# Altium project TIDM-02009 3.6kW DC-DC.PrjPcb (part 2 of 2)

## Sheet TIDM-02009_DCDC_Power Stage.SchDoc
size A2; DocumentNumber: 1; SheetNumber: 1; SheetTotal: 3; PageSetup: Record=PageOptions¦CenterHorizontal=True¦CenterVertical=True¦PrintScale=0.69¦XCorrection=1.00¦YCorrection=1.00¦PrintKind=0¦BorderSize=5000000¦LeftOffset=0¦BottomOffset=0¦Orientation=2¦PaperLength=1000¦PaperWidth=1000¦Scale=100¦PaperSource=15¦PrintQuality=600¦MediaType=1¦DitherType=10¦PaperKind=Letter¦PrintScaleMode=1
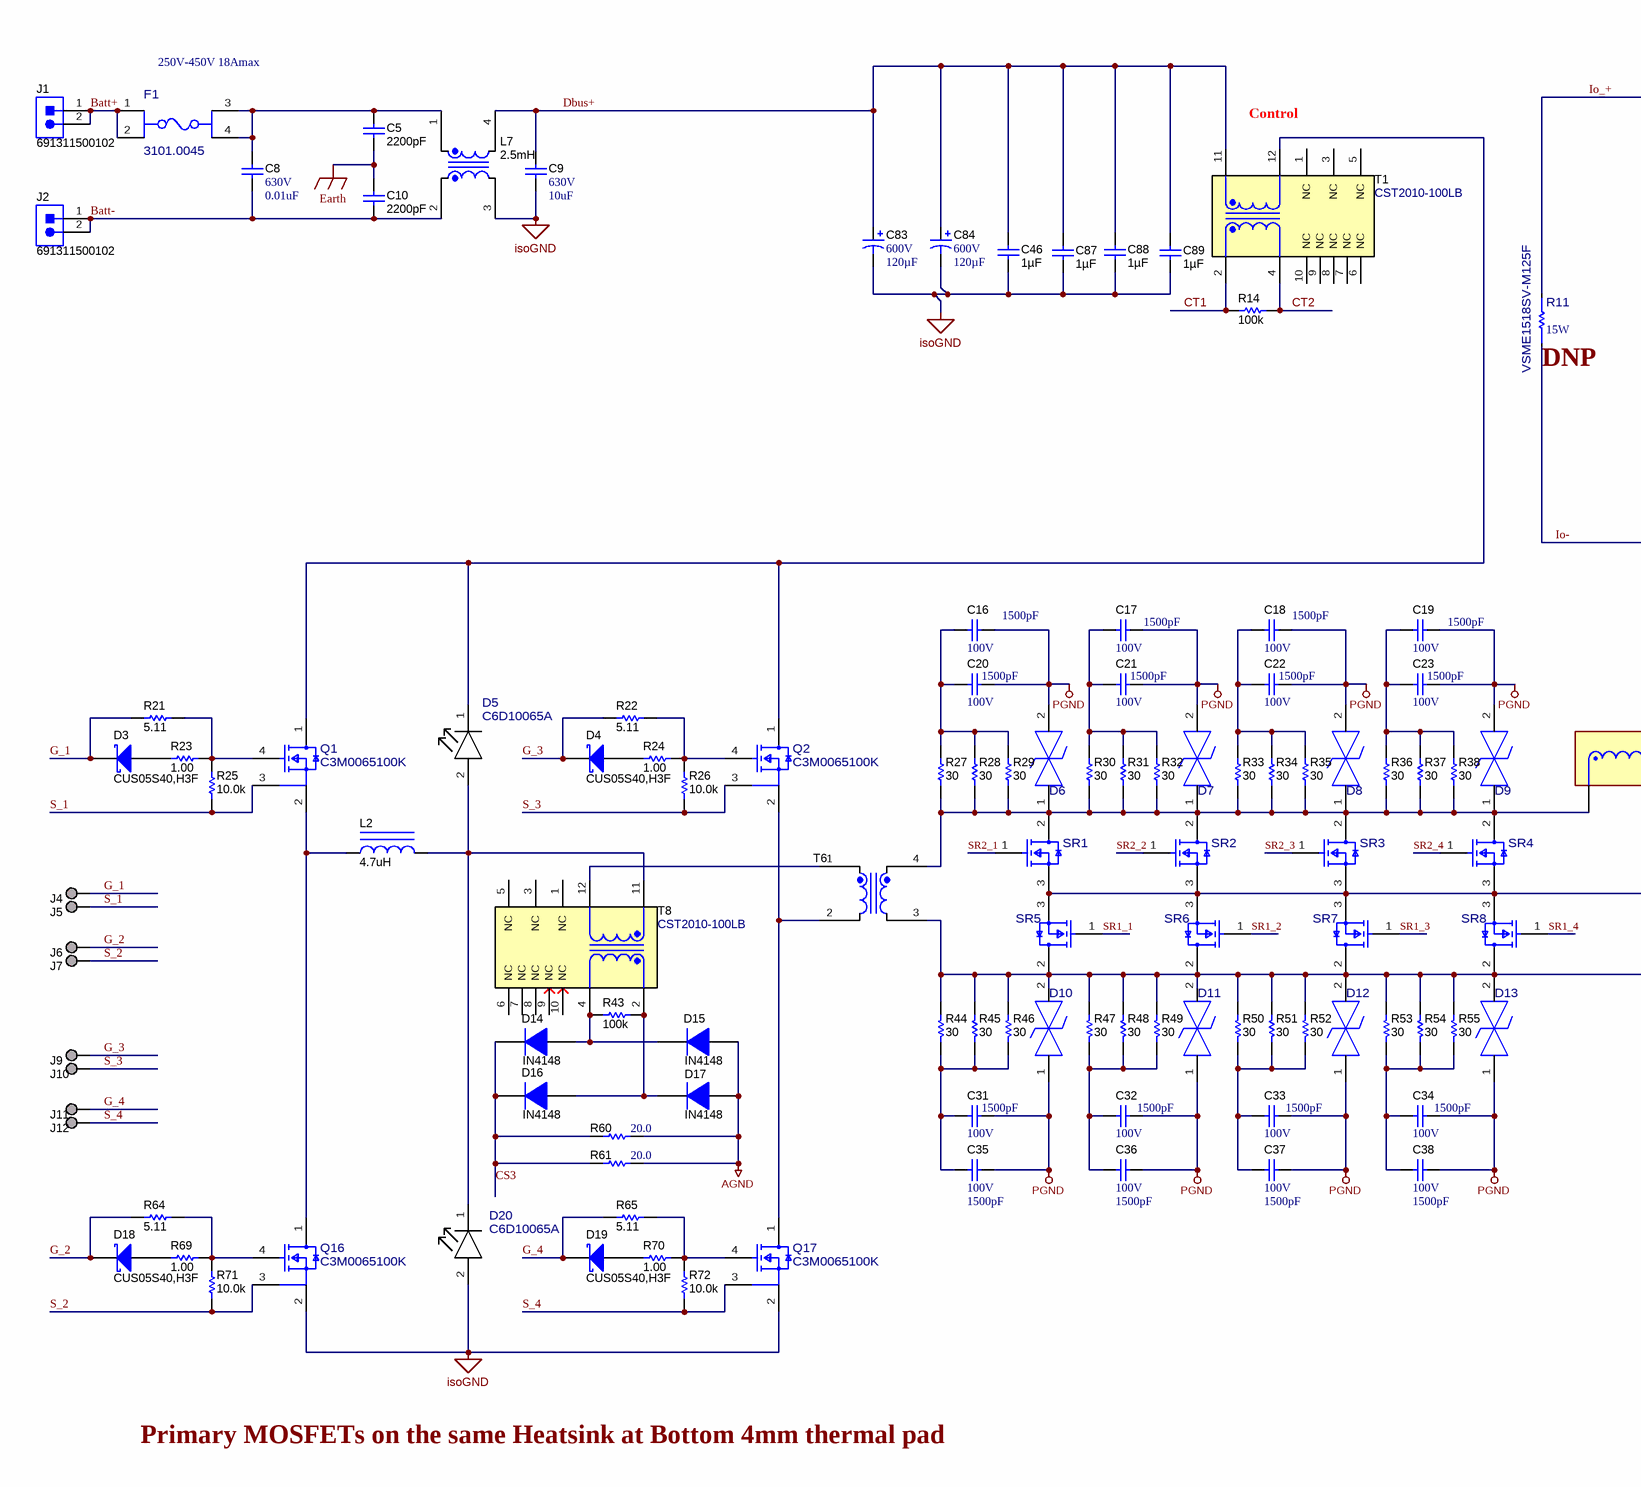
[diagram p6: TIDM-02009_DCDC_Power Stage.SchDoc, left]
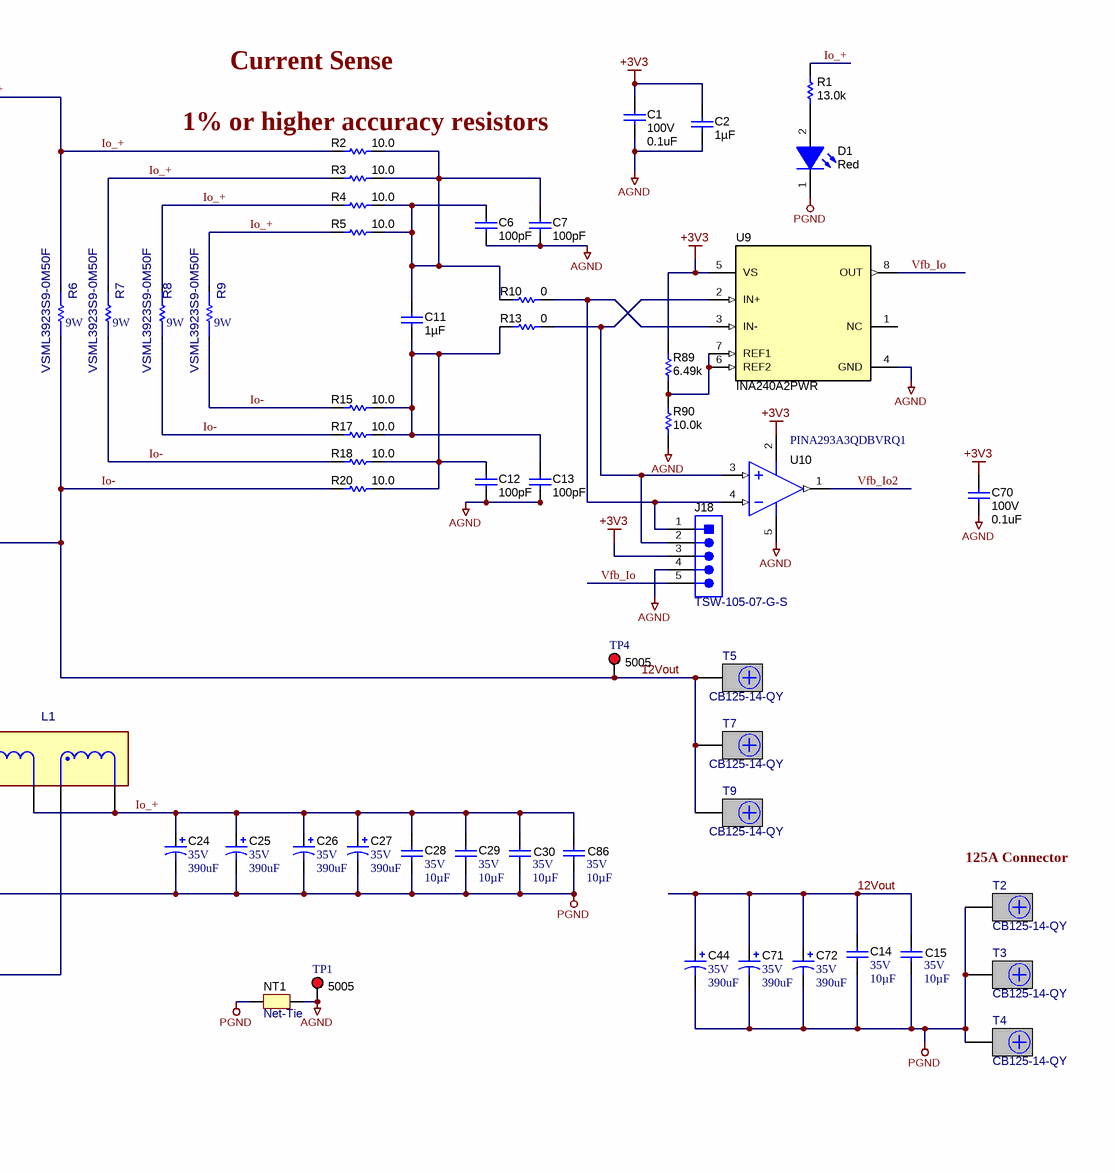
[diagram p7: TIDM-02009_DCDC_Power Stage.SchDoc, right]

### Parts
C1  VDC_V: 100V  ValueDisplayed: 0.1uF  [0603]  (hidden comment: GRM188R72A104KA35D)
C2  ValueDisplayed: 1µF  [0603]  (hidden comment: GRM188R71E105KA12D)
C5  ValueDisplayed: 2200pF  [E_900x700x900]  (hidden comment: DE6E3KJ222MN3A)
C6  ValueDisplayed: 100pF  [0603]  (hidden comment: 06035A101JAT2A)
C7  ValueDisplayed: 100pF  [0603]  (hidden comment: 06035A101JAT2A)
C8  VDC_V: 630V  ValueDisplayed: 0.01uF  [R73_1800x500x1100]  (hidden comment: R73PI21004000J)
C9  VDC_V: 630V  ValueDisplayed: 10uF  [B32926_42.5mm]  (hidden comment: B32926C3106K)
C10  ValueDisplayed: 2200pF  [E_900x700x900]  (hidden comment: DE6E3KJ222MN3A)
C11  ValueDisplayed: 1µF  [0603L]  (hidden comment: GRM188R71E105KA12D)
C12  ValueDisplayed: 100pF  [0603]  (hidden comment: 06035A101JAT2A)
C13  ValueDisplayed: 100pF  [0603]  (hidden comment: 06035A101JAT2A)
C14  VDC_V: 35V  ValueDisplayed: 10µF  [1210_270]  (hidden comment: GRM32ER7YA106KA12K)
C15  VDC_V: 35V  ValueDisplayed: 10µF  [1210_270]  (hidden comment: GRM32ER7YA106KA12K)
C16  VDC_V: 100V  ValueDisplayed: 1500pF  [1206]  (hidden comment: 12061C152KAT2A)
C17  VDC_V: 100V  ValueDisplayed: 1500pF  [1206]  (hidden comment: 12061C152KAT2A)
C18  VDC_V: 100V  ValueDisplayed: 1500pF  [1206]  (hidden comment: 12061C152KAT2A)
C19  VDC_V: 100V  ValueDisplayed: 1500pF  [1206]  (hidden comment: 12061C152KAT2A)
C20  VDC_V: 100V  ValueDisplayed: 1500pF  [1206]  (hidden comment: 12061C152KAT2A)
C21  VDC_V: 100V  ValueDisplayed: 1500pF  [1206]  (hidden comment: 12061C152KAT2A)
C22  VDC_V: 100V  ValueDisplayed: 1500pF  [1206]  (hidden comment: 12061C152KAT2A)
C23  VDC_V: 100V  ValueDisplayed: 1500pF  [1206]  (hidden comment: 12061C152KAT2A)
C24  VDC_V: 35V  ValueDisplayed: 390uF  [B41896_1250x2000]  (hidden comment: B41896C7397M000)
C25  VDC_V: 35V  ValueDisplayed: 390uF  [B41896_1250x2000]  (hidden comment: B41896C7397M000)
C26  VDC_V: 35V  ValueDisplayed: 390uF  [B41896_1250x2000]  (hidden comment: B41896C7397M000)
C27  VDC_V: 35V  ValueDisplayed: 390uF  [B41896_1250x2000]  (hidden comment: B41896C7397M000)
C28  VDC_V: 35V  ValueDisplayed: 10µF  [1210_270]  (hidden comment: GRM32ER7YA106KA12K)
C29  VDC_V: 35V  ValueDisplayed: 10µF  [1210_270]  (hidden comment: GRM32ER7YA106KA12K)
C30  VDC_V: 35V  ValueDisplayed: 10µF  [1210_270]  (hidden comment: GRM32ER7YA106KA12K)
C31  VDC_V: 100V  ValueDisplayed: 1500pF  [1206]  (hidden comment: 12061C152KAT2A)
C32  VDC_V: 100V  ValueDisplayed: 1500pF  [1206]  (hidden comment: 12061C152KAT2A)
C33  VDC_V: 100V  ValueDisplayed: 1500pF  [1206]  (hidden comment: 12061C152KAT2A)
C34  VDC_V: 100V  ValueDisplayed: 1500pF  [1206]  (hidden comment: 12061C152KAT2A)
C35  VDC_V: 100V  ValueDisplayed: 1500pF  [1206]  (hidden comment: 12061C152KAT2A)
C36  VDC_V: 100V  ValueDisplayed: 1500pF  [1206]  (hidden comment: 12061C152KAT2A)
C37  VDC_V: 100V  ValueDisplayed: 1500pF  [1206]  (hidden comment: 12061C152KAT2A)
C38  VDC_V: 100V  ValueDisplayed: 1500pF  [1206]  (hidden comment: 12061C152KAT2A)
C44  VDC_V: 35V  ValueDisplayed: 390uF  [B41896_1250x2000]  (hidden comment: B41896C7397M000)
C46  ValueDisplayed: 1µF  [2220_450]  (hidden comment: 2220Y6300105KXTWS2)
C70  VDC_V: 100V  ValueDisplayed: 0.1uF  [0603]  (hidden comment: GRM188R72A104KA35D)
C71  VDC_V: 35V  ValueDisplayed: 390uF  [B41896_1250x2000]  (hidden comment: B41896C7397M000)
C72  VDC_V: 35V  ValueDisplayed: 390uF  [B41896_1250x2000]  (hidden comment: B41896C7397M000)
C83  VDC_V: 600V  ValueDisplayed: 120µF  [Nichicon_3500x3500_Snap]  (hidden comment: LGN2X121MELC35)
C84  VDC_V: 600V  ValueDisplayed: 120µF  [Nichicon_3500x3500_Snap]  (hidden comment: LGN2X121MELC35)
C86  VDC_V: 35V  ValueDisplayed: 10µF  [1210_270]  (hidden comment: GRM32ER7YA106KA12K)
C87  ValueDisplayed: 1µF  [2220_450]  (hidden comment: 2220Y6300105KXTWS2)
C88  ValueDisplayed: 1µF  [2220_450]  (hidden comment: 2220Y6300105KXTWS2)
C89  ValueDisplayed: 1µF  [2220_450]  (hidden comment: 2220Y6300105KXTWS2)
D1  value Red  [WL-SMCW_RED_0805]  (hidden comment: 150080SS75000)
D3  CUS05S40,H3F  [SOD-323]
D4  CUS05S40,H3F  [SOD-323]
D5  C6D10065A  [FP-C6D10065A_TO-220-2-Recommended_Land_Pattern_Horizontal]
D6  TPSMB51CA  [FP-TPSMB51CA_DO214AA-MFG]  (value not drawn)
D7  TPSMB51CA  [FP-TPSMB51CA_DO214AA-MFG]  (value not drawn)
D8  TPSMB51CA  [FP-TPSMB51CA_DO214AA-MFG]  (value not drawn)
D9  TPSMB51CA  [FP-TPSMB51CA_DO214AA-MFG]  (value not drawn)
D10  TPSMB51CA  [FP-TPSMB51CA_DO214AA-MFG]  (value not drawn)
D11  TPSMB51CA  [FP-TPSMB51CA_DO214AA-MFG]  (value not drawn)
D12  TPSMB51CA  [FP-TPSMB51CA_DO214AA-MFG]  (value not drawn)
D13  TPSMB51CA  [FP-TPSMB51CA_DO214AA-MFG]  (value not drawn)
D14  IN4148  [SOD-123]
D15  IN4148  [SOD-123]
D16  IN4148  [SOD-123]
D17  IN4148  [SOD-123]
D18  CUS05S40,H3F  [SOD-323]
D19  CUS05S40,H3F  [SOD-323]
D20  C6D10065A  [FP-C6D10065A_TO-220-2-Recommended_Land_Pattern_Horizontal]
F1  3101.0045  [FP-3101.0045_PTH_FUSEHOLDERS-MFG]
J1  691311500102  [Wurth_691311500102]
J2  691311500102  [Wurth_691311500102]
J4  0312-0-15-15-34-27-10-0  [Mill-Max_0312-0-15-15-34-27-10-0]  (value not drawn)
J5  0312-0-15-15-34-27-10-0  [Mill-Max_0312-0-15-15-34-27-10-0]  (value not drawn)
J6  0312-0-15-15-34-27-10-0  [Mill-Max_0312-0-15-15-34-27-10-0]  (value not drawn)
J7  0312-0-15-15-34-27-10-0  [Mill-Max_0312-0-15-15-34-27-10-0]  (value not drawn)
J9  0312-0-15-15-34-27-10-0  [Mill-Max_0312-0-15-15-34-27-10-0]  (value not drawn)
J10  0312-0-15-15-34-27-10-0  [Mill-Max_0312-0-15-15-34-27-10-0]  (value not drawn)
J11  0312-0-15-15-34-27-10-0  [Mill-Max_0312-0-15-15-34-27-10-0]  (value not drawn)
J12  0312-0-15-15-34-27-10-0  [Mill-Max_0312-0-15-15-34-27-10-0]  (value not drawn)
J18  TSW-105-07-G-S  [TSW-105-07-X-S]
L1  VI-19158A  [FP-VI-19158A_PTH_INDUCTOR_47MM_39MM-MFG]  (value not drawn)
L2  ValueDisplayed: 4.7uH  [SER2915H]  (hidden comment: SER2915H-472KL)
L7  ValueDisplayed: 2.5mH  [WE-CMBNC_XL]  (hidden comment: 7448052303)
NT1  Net-Tie  [Net-Tie_50milWide_30milLong]  (net tie, no BOM)
Q1  C3M0065100K  [FP-C3M0065100K_TO247-4-MFG]
Q2  C3M0065100K  [FP-C3M0065100K_TO247-4-MFG]
Q16  C3M0065100K  [FP-C3M0065100K_TO247-4-MFG]
Q17  C3M0065100K  [FP-C3M0065100K_TO247-4-MFG]
R1  ValueDisplayed: 13.0k  [0603L]  (hidden comment: RC0603FR-0713KL)
R2  ValueDisplayed: 10.0  [0603L]  (hidden comment: CRCW060310R0FKEA)
R3  ValueDisplayed: 10.0  [0603L]  (hidden comment: CRCW060310R0FKEA)
R4  ValueDisplayed: 10.0  [0603L]  (hidden comment: CRCW060310R0FKEA)
R5  ValueDisplayed: 10.0  [0603L]  (hidden comment: CRCW060310R0FKEA)
R6  VSML3923S9-0M50F  Power_W: 9W  [FP-VSML3923S9-0M50F_SMT_10MM0_5MM75-MFG]
R7  VSML3923S9-0M50F  Power_W: 9W  [FP-VSML3923S9-0M50F_SMT_10MM0_5MM75-MFG]
R8  VSML3923S9-0M50F  Power_W: 9W  [FP-VSML3923S9-0M50F_SMT_10MM0_5MM75-MFG]
R9  VSML3923S9-0M50F  Power_W: 9W  [FP-VSML3923S9-0M50F_SMT_10MM0_5MM75-MFG]
R10  ValueDisplayed: 0  [0603L]  (hidden comment: CRCW06030000Z0EA)
R11  VSME1518SV-M125F  Power_W: 15W  [FP-VSME1518SV-M125F_SMT_RES_15MM0_18MM0-MFG]
R13  ValueDisplayed: 0  [0603L]  (hidden comment: CRCW06030000Z0EA)
R14  ValueDisplayed: 100k  [0603L]  (hidden comment: CRCW0603100KFKEA)
R15  ValueDisplayed: 10.0  [0603L]  (hidden comment: CRCW060310R0FKEA)
R17  ValueDisplayed: 10.0  [0603L]  (hidden comment: CRCW060310R0FKEA)
R18  ValueDisplayed: 10.0  [0603L]  (hidden comment: CRCW060310R0FKEA)
R20  ValueDisplayed: 10.0  [0603L]  (hidden comment: CRCW060310R0FKEA)
R21  ValueDisplayed: 5.11  [0603L]  (hidden comment: CRCW06035R11FKEA)
R22  ValueDisplayed: 5.11  [0603L]  (hidden comment: CRCW06035R11FKEA)
R23  ValueDisplayed: 1.00  [0603L]  (hidden comment: RC0603FR-071RL)
R24  ValueDisplayed: 1.00  [0603L]  (hidden comment: RC0603FR-071RL)
R25  ValueDisplayed: 10.0k  [0603L]  (hidden comment: CRCW060310K0FKEA)
R26  ValueDisplayed: 10.0k  [0603L]  (hidden comment: CRCW060310K0FKEA)
R27  ValueDisplayed: 30  [2010L]  (hidden comment: CRCW201030R0JNEF)
R28  ValueDisplayed: 30  [2010L]  (hidden comment: CRCW201030R0JNEF)
R29  ValueDisplayed: 30  [2010L]  (hidden comment: CRCW201030R0JNEF)
R30  ValueDisplayed: 30  [2010L]  (hidden comment: CRCW201030R0JNEF)
R31  ValueDisplayed: 30  [2010L]  (hidden comment: CRCW201030R0JNEF)
R32  ValueDisplayed: 30  [2010L]  (hidden comment: CRCW201030R0JNEF)
R33  ValueDisplayed: 30  [2010L]  (hidden comment: CRCW201030R0JNEF)
R34  ValueDisplayed: 30  [2010L]  (hidden comment: CRCW201030R0JNEF)
R35  ValueDisplayed: 30  [2010L]  (hidden comment: CRCW201030R0JNEF)
R36  ValueDisplayed: 30  [2010L]  (hidden comment: CRCW201030R0JNEF)
R37  ValueDisplayed: 30  [2010L]  (hidden comment: CRCW201030R0JNEF)
R38  ValueDisplayed: 30  [2010L]  (hidden comment: CRCW201030R0JNEF)
R43  ValueDisplayed: 100k  [0603L]  (hidden comment: CRCW0603100KFKEA)
R44  ValueDisplayed: 30  [2010L]  (hidden comment: CRCW201030R0JNEF)
R45  ValueDisplayed: 30  [2010L]  (hidden comment: CRCW201030R0JNEF)
R46  ValueDisplayed: 30  [2010L]  (hidden comment: CRCW201030R0JNEF)
R47  ValueDisplayed: 30  [2010L]  (hidden comment: CRCW201030R0JNEF)
R48  ValueDisplayed: 30  [2010L]  (hidden comment: CRCW201030R0JNEF)
R49  ValueDisplayed: 30  [2010L]  (hidden comment: CRCW201030R0JNEF)
R50  ValueDisplayed: 30  [2010L]  (hidden comment: CRCW201030R0JNEF)
R51  ValueDisplayed: 30  [2010L]  (hidden comment: CRCW201030R0JNEF)
R52  ValueDisplayed: 30  [2010L]  (hidden comment: CRCW201030R0JNEF)
R53  ValueDisplayed: 30  [2010L]  (hidden comment: CRCW201030R0JNEF)
R54  ValueDisplayed: 30  [2010L]  (hidden comment: CRCW201030R0JNEF)
R55  ValueDisplayed: 30  [2010L]  (hidden comment: CRCW201030R0JNEF)
R60  ValueDisplayed: 20.0  [1206L]  (hidden comment: RC1206FR-0720RL)
R61  ValueDisplayed: 20.0  [1206L]  (hidden comment: RC1206FR-0720RL)
R64  ValueDisplayed: 5.11  [0603L]  (hidden comment: CRCW06035R11FKEA)
R65  ValueDisplayed: 5.11  [0603L]  (hidden comment: CRCW06035R11FKEA)
R69  ValueDisplayed: 1.00  [0603L]  (hidden comment: RC0603FR-071RL)
R70  ValueDisplayed: 1.00  [0603L]  (hidden comment: RC0603FR-071RL)
R71  ValueDisplayed: 10.0k  [0603L]  (hidden comment: CRCW060310K0FKEA)
R72  ValueDisplayed: 10.0k  [0603L]  (hidden comment: CRCW060310K0FKEA)
R89  ValueDisplayed: 6.49k  [0603]  (hidden comment: RC0603FR-076K49L)
R90  ValueDisplayed: 10.0k  [0603]  (hidden comment: ERJ-3EKF1002V)
SR1  IPP120N08S403AKSA1_hr  [FP-IPP120N08S403AKSA1_hr_TO220-MFG]  (value not drawn)
SR2  IPP120N08S403AKSA1_hr  [FP-IPP120N08S403AKSA1_hr_TO220-MFG]  (value not drawn)
SR3  IPP120N08S403AKSA1_hr  [FP-IPP120N08S403AKSA1_hr_TO220-MFG]  (value not drawn)
SR4  IPP120N08S403AKSA1_hr  [FP-IPP120N08S403AKSA1_hr_TO220-MFG]  (value not drawn)
SR5  IPP120N08S403AKSA1_hr  [FP-IPP120N08S403AKSA1_hr_TO220-MFG]  (value not drawn)
SR6  IPP120N08S403AKSA1_hr  [FP-IPP120N08S403AKSA1_hr_TO220-MFG]  (value not drawn)
SR7  IPP120N08S403AKSA1_hr  [FP-IPP120N08S403AKSA1_hr_TO220-MFG]  (value not drawn)
SR8  IPP120N08S403AKSA1_hr  [FP-IPP120N08S403AKSA1_hr_TO220-MFG]  (value not drawn)
T1  CST2010-100LB  [CST2010]
T2  CB125-14-QY  [Panduit_CB125-14-QY]
T3  CB125-14-QY  [Panduit_CB125-14-QY]
T4  CB125-14-QY  [Panduit_CB125-14-QY]
T5  CB125-14-QY  [Panduit_CB125-14-QY]
T6  7G08B-100M-R  [IND_7G08B]  (value not drawn)
T7  CB125-14-QY  [Panduit_CB125-14-QY]
T8  CST2010-100LB  [CST2010]
T9  CB125-14-QY  [Panduit_CB125-14-QY]
TP1  5005  [Keystone5005]
TP4  5005  [Keystone5005]
U9  INA240A2PWR  [PW0008A_L]
U10  PINA293A3QDBVRQ1  [DBV0005A_N]

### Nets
+3V3: C1.1 C2.1 C70.1 J18.3 R89.2 U9.5(VS) U10.2(GND)
AGND: C1.2 C2.2 C6.2 C7.2 C12.2 C13.2 C70.2 D15.2(A) D17.2(A) J18.4 NT1.2 R60.2 R61.2 R90.1 TP1.1 U9.4(GND) U10.5(V+)
Earth: C5.2 C10.1
isoGND: C9.2 C46.2 C83.2(-) C84.2(-) C87.2 C88.2 C89.2 D20.2(ANODE) L7.3 Q16.2(S) Q17.2(S)
PGND: C14.2 C15.2 C16.1 C17.1 C18.1 C19.1 C20.1 C21.1 C22.1 C23.1 C24.2(-) C25.2(-) C26.2(-) C27.2(-) C28.2 C29.2 C30.2 C31.1 C32.1 C33.1 C34.1 C35.1 C36.1 C37.1 C38.1 C44.2(-) C71.2(-) C72.2(-) C86.2 D1.1(K) D6.2 D7.2 D8.2 D9.2 D10.1 D11.1 D12.1 D13.1 NT1.1 SR1.3(SOURCE) SR2.3(SOURCE) SR3.3(SOURCE) SR4.3(SOURCE) SR5.3(SOURCE) SR6.3(SOURCE) SR7.3(SOURCE) SR8.3(SOURCE) T2.1 T3.1 T4.1
12Vout: C14.1 C15.1 C44.1(+) C71.1(+) C72.1(+) R6.1 R7.1 R8.1 R9.1 R11.1 R15.1 R17.1 R18.1 R20.1 T5.1 T7.1 T9.1 TP4.1  [also labelled Io-]
Batt+: F1.1 F1.2 J1.1 J1.2
Batt-: C8.2 C10.2 J2.1 J2.2 L7.2
CS3: D14.1(K) D16.1(K) R60.1 R61.1
CT1: R14.1 T1.2
CT2: R14.2 T1.4
Dbus+: C9.1 C46.1 C83.1(+) C84.1(+) C87.1 C88.1 C89.1 L7.4 T1.11
G_1: D3.1(K) J4.1 R21.1
G_2: D18.1(K) J6.1 R64.1
G_3: D4.1(K) J9.1 R22.1
G_4: D19.1(K) J11.1 R65.1
Io_+: C24.1(+) C25.1(+) C26.1(+) C27.1(+) C28.1 C29.1 C30.1 C86.1 D10.2 D11.2 D12.2 D13.2 L1.2 L1.3 L1.4 R1.2 R2.1 R3.1 R4.1 R5.1 R6.2 R7.2 R8.2 R9.2 R11.2 R44.1 R45.1 R46.1 R47.1 R48.1 R49.1 R50.1 R51.1 R52.1 R53.1 R54.1 R55.1 SR5.2(DRAIN) SR6.2(DRAIN) SR7.2(DRAIN) SR8.2(DRAIN) T6.3
S_1: J5.1 Q1.3(S) R25.1
S_2: J7.1 Q16.3(S) R71.1
S_3: J10.1 Q2.3(S) R26.1
S_4: J12.1 Q17.3(S) R72.1
SR1_1: SR5.1(GATE)
SR1_2: SR6.1(GATE)
SR1_3: SR7.1(GATE)
SR1_4: SR8.1(GATE)
SR2_1: SR1.1(GATE)
SR2_2: SR2.1(GATE)
SR2_3: SR3.1(GATE)
SR2_4: SR4.1(GATE)
Vfb_Io: J18.5 U9.8(OUT)
Vfb_Io2: U10.1(OUT)
NetC5_1: C5.1 C8.1 F1.3 F1.4 L7.1
NetC6_1: C6.1 C7.1 C11.1 R2.2 R3.2 R4.2 R5.2 R10.2
NetC11_2: C11.2 C12.1 C13.1 R13.2 R15.2 R17.2 R18.2 R20.2
NetC16_2: C16.2 C20.2 R27.2 R28.2 R29.2
NetC17_2: C17.2 C21.2 R30.2 R31.2 R32.2
NetC18_2: C18.2 C22.2 R33.2 R34.2 R35.2
NetC19_2: C19.2 C23.2 R36.2 R37.2 R38.2
NetC31_2: C31.2 C35.2 R44.2 R45.2 R46.2
NetC32_2: C32.2 C36.2 R47.2 R48.2 R49.2
NetC33_2: C33.2 C37.2 R50.2 R51.2 R52.2
NetC34_2: C34.2 C38.2 R53.2 R54.2 R55.2
NetD1_2: D1.2(A) R1.1
NetD3_2: D3.2(A) R23.1
NetD4_2: D4.2(A) R24.1
NetD5_1: D5.1(CATHODE) Q1.1(D) Q2.1(D) T1.12
NetD5_2: D5.2(ANODE) D20.1(CATHODE) L2.2 T8.11
NetD6_1: D6.1 D7.1 D8.1 D9.1 L1.1 R27.1 R28.1 R29.1 R30.1 R31.1 R32.1 R33.1 R34.1 R35.1 R36.1 R37.1 R38.1 SR1.2(DRAIN) SR2.2(DRAIN) SR3.2(DRAIN) SR4.2(DRAIN) T6.4
NetD14_2: D14.2(A) D15.1(K) R43.1 T8.4
NetD16_2: D16.2(A) D17.1(K) R43.2 T8.2
NetD18_2: D18.2(A) R69.1
NetD19_2: D19.2(A) R70.1
NetJ18_1: J18.1 R10.1 U9.3(IN-) U10.4(VIN-)
NetJ18_2: J18.2 R13.1 U9.2(IN+) U10.3(VIN+)
NetL2_1: L2.1 Q1.2(S) Q16.1(D)
NetQ1_4: Q1.4(G) R21.2 R23.2 R25.2
NetQ2_2: Q2.2(S) Q17.1(D) T6.2
NetQ2_4: Q2.4(G) R22.2 R24.2 R26.2
NetQ16_4: Q16.4(G) R64.2 R69.2 R71.2
NetQ17_4: Q17.4(G) R65.2 R70.2 R72.2
NetR89_1: R89.1 R90.2 U9.6(REF2) U9.7(REF1)
NetT6_1: T6.1 T8.12

Not connected (* = marked no-connect by the designer): T1 1(NC) 3(NC) 5(NC) 6(NC) 7(NC) 8(NC) 9(NC) 10(NC); T8 1(NC) 3(NC) 5(NC) 6(NC) 7(NC) 8(NC) 9(NC) 10(NC); U9 1(NC)

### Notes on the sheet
- (near F1) 250V-450V 18Amax
- Current Sense
- (near T1) Control
- (near R2) 1% or higher accuracy resistors
- (near R11) DNP
- (near T2) 125A Connector
- Primary MOSFETs on the same Heatsink at Bottom 4mm thermal pad

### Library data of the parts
C1 C70 = CMP-0007469-4: CAP, CERM, 0.1 uF, 100 V, +/- 10%, X7R, 0603; Manufacturer: MuRata; TaMin_C: -55°C; Polarized: N; SizeAreaWB_mm2: 4.68; Value1: Unknown; U/M: EA; Value: 0.1uF; TaMax_C: 125°C; SizeZ_mm: 1; SizeX_mm: 1.6; SizeY_mm: 0.8; SizeArea_mm2: 1.28; Cap_F: 100nF; AEC Category: Q200
C2 = GRM188R71E105KA12D: CAP, CERM, 1 µF, 25 V, +/- 10%, X7R, 0603; Manufacturer: MuRata; Polarized: N; CompType: Capacitor; Value: 1uF; U/M: EA; Cap_F: 0.000001; Tolerance_%: 10; Value1: Unknown; VDC_V: 25; Value2: 25V; TaMin_C: -55; TaMax_C: 125; SizeArea_mm2: 1.28; SizeAreaWB_mm2: 4.68; SizeX_mm: 1.6; SizeY_mm: 0.8; SizeZ_mm: 1; AEC Category: Q200
C5 C10 = DE6E3KJ222MN3A: CAP, CERM, 2200 pF, 300 V, +/- 20%, E, TH, 2- Leads, Body 9x7mm, Pin Spacing 7.5mm; Manufacturer: MuRata; Polarized: N; CompType: Capacitor; Value: 2200pF; U/M: EA; Cap_F: 0.0000000022; Tolerance_%: 20; Value1: Unknown; VDC_V: 300; Value2: 300V; TaMin_C: -40; TaMax_C: 125; Cap_Case: 9x7x9mm; SizeArea_mm2: 63; SizeAreaWB_mm2: 99; SizeX_mm: 9; SizeY_mm: 7; SizeZ_mm: 12; AEC Category: Q200
C6 C7 C12 C13 = 06035A101JAT2A: CAP, CERM, 100 pF, 50 V,+/- 5%, C0G/NP0, 0603; Manufacturer: AVX; Polarized: N; CompType: Capacitor; Value: 100pF; U/M: EA; Cap_F: 0.0000000001; Tolerance_%: 5; ESR_ohm: 0.119; Value1: 0.119 ohm; VDC_V: 50; Value2: 50V; TaMin_C: -55; TaMax_C: 125; SizeArea_mm2: 1.28; SizeAreaWB_mm2: 4.68; SizeX_mm: 1.6; SizeY_mm: 0.8; SizeZ_mm: 1; AEC Category: Q200; Green_Lifecycle: Active; Green_REACh: Passed
C8 = CMP-0012561-1: CAP, Film, 0.01 uF, 630 V, +/- 5%, AEC-Q200 Grade 2, TH; Manufacturer: Kemet; TaMin_C: -55°C; Polarized: N; SizeAreaWB_mm2: 140; Value1: Unknown; U/M: EA; Value: 0.01uF; TaMax_C: 105°C; SizeZ_mm: 11.1; SizeX_mm: 18; SizeY_mm: 5; Cap_Case: 18x5x11mm; SizeArea_mm2: 90; AEC Qualified: Y; Cap_F: 10nF; AEC Grade: 2; AEC Category: Q200
C9 = CMP-0012443-3: CAP, Film, 10 uF, 630 V, +/- 10%, TH; Manufacturer: TDK; Polarized: N; SizeAreaWB_mm2: 1305; Value1: Unknown; Value: 10uF; TaMax_C: 110°C; SizeZ_mm: 42.5; SizeX_mm: 28; SizeY_mm: 41.5; SizeArea_mm2: 1162; Cap_F: 10µF; AEC Category: Q200
C11 = GRM188R71E105KA12D: CAP, CERM, 1 µF, 25 V, +/- 10%, X7R, 0603; Manufacturer: MuRata; Polarized: N; CompType: Capacitor; Value: 1uF; U/M: EA; Cap_F: 0.000001; Tolerance_%: 10; Value1: Unknown; VDC_V: 25; Value2: 25V; TaMin_C: -55; TaMax_C: 125; Cap_Case: 0603; SizeArea_mm2: 1.28; SizeAreaWB_mm2: 4.68; SizeX_mm: 1.6; SizeY_mm: 0.8; SizeZ_mm: 1; AEC Category: Q200
C14 C15 C28-C30 C86 = CMP-0081639-1: CAP, CERM, 10 µF, 35 V,+/- 10%, X7R, 1210; Manufacturer: MuRata; TaMin_C: -55°C; ESR_ohm: 1m; Polarized: N; SizeAreaWB_mm2: 14.7; Value1: 0.001 ohm; U/M: EA; Value: 10uF; TaMax_C: 125°C; SizeZ_mm: 2.7; SizeX_mm: 3.2; SizeY_mm: 2.5; Cap_Case: 1210; SizeArea_mm2: 8; IRMS_A: 6A; AEC Category: Q200
C16-C23 C31-C38 = CMP-0008490-2: CAP, CERM, 1500 pF, 100 V, +/- 10%, X7R, 1206; Manufacturer: AVX; TaMin_C: -55°C; ESR_ohm: 0.338; Polarized: N; SizeAreaWB_mm2: 10.92; Value1: 0.338 ohm; U/M: EA; Value: 1500pF; TaMax_C: 125°C; SizeZ_mm: 1.35; SizeX_mm: 3.2; SizeY_mm: 1.6; SizeArea_mm2: 5.12; Cap_F: 1.5nF; AEC Category: Q200
C24-C27 C44 C71 C72 = CMP-0010314-2: CAP, AL, 390 uF, 35 V, +/- 20%, 0.055 ohm, AEC-Q200 Grade 1, TH; Manufacturer: TDK; TaMin_C: -55°C; ESR_ohm: 0.055; Polarized: Y; SizeAreaWB_mm2: 210.25; U/M: EA; Value: 390uF; TaMax_C: 125°C; SizeZ_mm: 22; SizeX_mm: 12.5; Cap_Case: 12.5x20mm; SizeArea_mm2: 156.25; CompType: Capacitor; Cap_F: 390µF; IRMS_A: 1.82A; AEC Grade: 1; AEC Category: Q200
C46 C87-C89 = 2220Y6300105KXTWS2: CAP, CERM, 1 µF, 630 V,+/- 10%, X7R, AEC-Q200 Grade 1, 2220; Manufacturer: Knowles Capacitors; Polarized: N; CompType: Capacitor; Value: 1uF; U/M: EA; Cap_F: 0.000001; Tolerance_%: 10; VDC_V: 630; Value2: 630V; TaMin_C: -55; TaMax_C: 125; Cap_Case: 2220; SizeArea_mm2: 28.5; SizeAreaWB_mm2: 53.9; SizeX_mm: 5.7; SizeY_mm: 5; SizeZ_mm: 4.5; AEC Category: Q200; AEC Qualified: Y; AEC Grade: 1
C83 C84 = CMP-0083862-1: CAP, AL, 120 µF, 600 V, +/- 20%, TH; Manufacturer: Nichicon; TaMin_C: -25°C; Polarized: Y; SizeAreaWB_mm2: 1369; U/M: EA; Value: 120uF; TaMax_C: 105°C; SizeZ_mm: 37; SizeX_mm: 35; Cap_Case: 35x35mm; SizeArea_mm2: 1225; CompType: Capacitor; AEC Qualified: N; IRMS_A: 740mA; AEC Category: Q200
D1 = 150080SS75000: LED, Red, SMD; Manufacturer: Wurth Elektronik; Type: AlInGaP; Vf_V: 1.9; Value2: 1.9V; Io_A: 0.03; Vr_V: 5; Ir_A: 2.5e-005; Tjmax_C: 85; Power_TotalModule: 0.072; Value1: 0.072W; Angle: 140; U/M: EA; Green_Lifecycle: Active; Green_REACh: Passed
D3 D4 D18 D19 = CUS05S40,H3F: Diode, Schottky, 40 V, 0.5 A, SOD-323; Manufacturer: Toshiba; U/M: EA; Vf_V: 0.6; Value: 40V; Value1: 0.5A; Value2: 0.6V; Io_A: 0.5; Vr_V: 40; TJmax_C: 125; SizeAreaWB_mm2: 8.695; SizeArea_mm2: 3.645; SizeX_mm: 2.7; SizeY_mm: 1.35; SizeZ_mm: 1; AEC Category: Q101; AEC Qualified: N; Green_Lifecycle: Not Set; Green_REACh: Incomplete
D5 D20 = CMP-0088257-2: Diode Silicon Carbide Schottky 650V 37A (DC) Through Hole TO-220-2; Manufacturer: Wolfspeed; AEC Qualified: No; Symbol Name: SYM-C6D10065A; SizeZ_mm: 19.431mm; TJmax_C: 175°C; AEC Category: Q101
D6-D13 = CMP-0087693-1: 70.1V Clamp 8.7A Ipp Tvs Diode Surface Mount DO-214AA (SMBJ); Manufacturer: Littelfuse; SizeZ_mm: 2.44mm; AEC Qualified: Yes
D14-D17 = 1N4148W-7-F: Diode, Ultrafast, 100 V, 0.15 A, SOD-123; Manufacturer: Diodes Inc.; U/M: EA; Vf_V: 1.25; Value: 100V; Value1: 0.15A; Value2: 1.25V; Io_A: 0.15; Vr_V: 100; TJmax_C: 150; SizeAreaWB_mm2: 13.095; SizeArea_mm2: 6.545; SizeX_mm: 3.85; SizeY_mm: 1.7; SizeZ_mm: 1.35; AEC Category: Q101
F1 = CMP-0088902-1: FUSE HLDR CARTRIDGE 500V 16A PCB; Manufacturer: Schurter; Number Of Fuses: 1; Conn Orientation: Vertical; AEC Qualified: No; Standoff Height: 0.6mm; TaMax_C: +85°C; SizeZ_mm: 37.6mm; TaMin_C: -40°C
J1 J2 = CMP-0084907-1: Terminal Block, 2 Pos, 5.08mm, Tin, TH; Manufacturer: Wurth Elektronik; Row_Count: 1; Voltage_V: 300V; Shrouded: Y; Gender: Male; Current_A: 20A; Pitch_mm: 5.08
J4-J7 J9-J12 = CMP-0055026-1: Manufacturer: Mill-Max; CNHeader: FALSE; Green_Lifecycle: Active; Gender: Female; Green_REACh: Passed; CompType: Pin Receptacle; ContactFinish: Gold
J18 = CMP-0075411-1: Header, 100mil, 5x1, Gold, TH; Manufacturer: Samtec; Pitch_mm: 2.54; Cert_VDE: N; Gender: Male; Cert_CSA: Y; Voltage_V: 550V; Green_REACh: Passed; Current_A: 6.3A; CT: False; Green_Lifecycle: Active; Row_Count: 1; CNHeader: True
L1 = CMP-0088176-1: Fixed Inductor of Cyntec; SizeZ_mm: 42mm; Ind_H: 1.3µH; DCR_ohm: 170µ; AEC Qualified: No
L2 = CMP-0060854-1: Inductor, Shielded E Core, Ferrite, 4.7 uH, 30 A, 0.00186 ohm, SMD; Manufacturer: Coilcraft; Isat: 50.1A @ 30% inductance drop; Irms: 30A @ 40C rise; Green_Lifecycle: Not Set; SizeAreaWB_mm2: 651.82; DCR_ohm: 1.86m; Green_REACh: Incomplete; Value: 4.7uH; Imax_A: 30A; SizeZ_mm: 15.36; SizeX_mm: 27.9; SizeY_mm: 19.8; SizeArea_mm2: 552.42; Ind_H: 4.7µH; AEC Category: Q200
L7 = 7448052303: CMC 2.5MH 25A 2LN TH; PartNumber: 7448052502; Manufacturer: Wurth Elektronik; SymbolCreator: a0799628; CompType: Coupled Inductor
NT1 = CMP-0078142-2: Single point connection between nets.
Q1 Q2 Q16 Q17 = CMP-0088256-2: SiC N-Channel MOSFET, 35 A, 1000 V C3M, 4-Pin TO-247; Manufacturer: Wolfspeed; IdsMax_A: 35A; SizeZ_mm: 5.21mm; Rdson45_ohm: 0.065; ChMode: False; AEC Qualified: No; VdsMax_V: 1kV
R1 = RC0603FR-0713KL: RES, 13.0 k, 1%, 0.1 W, 0603; Manufacturer: Yageo America; CompType: Resistor; Value: 13.0k; Res_ohm: 13000; Value_Code: 13k0; Tolerance_%: 1; Power_W: 0.1; Value2: 0.1W; VDC_V: 150; TempCo: 200 ppm/C; SizeArea_mm2: 1.28; SizeX_mm: 1.6; SizeY_mm: 0.8; EIA_Code: E96; U/M: EA; AEC Category: Q200
R2-R5 R15 R17 R18 R20 = CRCW060310R0FKEA: RES, 10.0, 1%, 0.1 W, 0603; Manufacturer: Vishay-Dale; CompType: Resistor; Value: 10.0; Res_ohm: 10; Value_Code: 10R0; Tolerance_%: 1; Power_W: 0.1; Value2: 0.1W; VDC_V: 75; TempCo: 100 ppm/C; SizeArea_mm2: 1.28; SizeX_mm: 1.6; SizeY_mm: 0.8; EIA_Code: E96; U/M: EA; AEC Category: Q200; Green_Lifecycle: Active; Green_REACh: Passed
R6-R9 = CMP-0087912-1: 500 µOhms ±1% 9W Chip Resistor Nonstandard Current Sense, Pulse Withstanding; Manufacturer: Cyntec; TempCo: 75ppm/°C; AEC Grade: Grade 0; AEC Qualified: Yes; SizeZ_mm: 1.85mm; Symbol Name: SYM-VSML3923S9-0M50F
R10 R13 = CRCW06030000Z0EA: RES, 0, 5%, 0.1 W, 0603; Manufacturer: Vishay-Dale; CompType: Resistor; Value: 0; Value_Code: 0000; Tolerance_%: 5; Power_W: 0.1; Value2: 0.1W; VDC_V: 75; TempCo: 200 ppm/C; SizeArea_mm2: 1.28; SizeX_mm: 1.6; SizeY_mm: 0.8; SizeZ_mm: 1; EIA_Code: E24; U/M: EA; AEC Category: Q200; Green_Lifecycle: Active; Green_REACh: Passed
R11 = CMP-0087913-1: 125uOhm, 15W, high power, low ESL current shunt resistor; Manufacturer: Cyntec; TempCo: 100ppm/°C; Tolerance_%: 1%; Symbol Name: SYM-VSME1518SV-M125F; AEC Qualified: No; SizeZ_mm: 2.75mm; AEC Grade: NA
R14 R43 = CRCW0603100KFKEA: RES, 100 k, 1%, 0.1 W, 0603; Manufacturer: Vishay-Dale; CompType: Resistor; Value: 100k; Res_ohm: 100000; Tolerance_%: 1; Power_W: 0.1; Value2: 0.1W; VDC_V: 75; TempCo: 100 ppm/C; SizeArea_mm2: 1.28; SizeX_mm: 1.6; SizeY_mm: 0.8; EIA_Code: E96; U/M: EA; AEC Category: Q200; Green_Lifecycle: Active; Green_REACh: Passed
R21 R22 R64 R65 = CRCW06035R11FKEA: RES, 5.11, 1%, 0.1 W, 0603; Manufacturer: Vishay-Dale; CompType: Resistor; Value: 5.11; Value_Code: 5R11; Tolerance_%: 1; Power_W: 0.1; Value2: 0.1W; VDC_V: 75; TempCo: 100 ppm/C; SizeArea_mm2: 1.28; SizeX_mm: 1.6; SizeY_mm: 0.8; EIA_Code: E96; U/M: EA; AEC Category: Q200; Green_Lifecycle: Active; Green_REACh: Passed
R23 R24 R69 R70 = RC0603FR-071RL: RES, 1.00, 1%, 0.1 W, 0603; Manufacturer: Yageo America; CompType: Resistor; Value: 1.00; Res_ohm: 1; Value_Code: 1R00; Power_W: 0.1; Value2: 0.1W; VDC_V: 150; TempCo: 200 ppm/C; SizeArea_mm2: 1.28; SizeX_mm: 1.6; SizeY_mm: 0.8; EIA_Code: E96; U/M: EA; AEC Category: Q200; Green_Lifecycle: Active; Green_REACh: Passed
R25 R26 R71 R72 = CRCW060310K0FKEA: RES, 10.0 k, 1%, 0.1 W, 0603; Manufacturer: Vishay-Dale; CompType: Resistor; Value: 10.0k; Res_ohm: 10000; Value_Code: 10k0; Tolerance_%: 1; Power_W: 0.1; Value2: 0.1W; VDC_V: 75; TempCo: 100 ppm/C; SizeArea_mm2: 1.28; SizeX_mm: 1.6; SizeY_mm: 0.8; EIA_Code: E96; U/M: EA; AEC Category: Q200; Green_Lifecycle: Active; Green_REACh: Passed
R27-R38 R44-R55 = CRCW201030R0JNEF: RES, 30, 5%, 0.75 W, AEC-Q200 Grade 0, 2010; Manufacturer: Vishay-Dale; CompType: Resistor; Value: 30; Value_Code: 30R0; Tolerance_%: 5; Power_W: 0.75; Value2: 0.75W; VDC_V: 400; TempCo: 200 ppm/C; SizeArea_mm2: 12.5; SizeY_mm: 2.5; SizeZ_mm: 1.66; EIA_Code: E24; U/M: EA; AEC Category: Q200; AEC Qualified: Y; AEC Grade: 0
R60 R61 = CMP-0018067-2: RES, 20.0, 1%, 0.25 W, 1206; Manufacturer: Yageo America; Power_W: 250mW; TempCo: 100 ppm/C; Value_Code: 20R0; U/M: EA; Value: 20.0; EIA_Code: E96; Res_ohm: 20; SizeX_mm: 3.2; SizeY_mm: 1.6; SizeZ_mm: 1.35; Value2: 0.25W; SizeArea_mm2: 5.12; VDC_V: 200V; AEC Category: Q200
R89 = CMP-0023250-5: RES, 6.49 k, 1%, 0.1 W, 0603; Manufacturer: Yageo; Power_W: 100mW; TempCo: 100 ppm/C; Value_Code: 6k49; Value: 6.49k; EIA_Code: E96; SizeX_mm: 1.6; SizeY_mm: 0.8; SizeZ_mm: 1; Value2: 0.1W; SizeArea_mm2: 1.28; AEC Qualified: N; VDC_V: 75V; AEC Category: Q200; SizeAreaWB_mm2: 4.68
R90 = CMP-0022684-3: RES, 10.0 k, 1%, 0.1 W, 0603; Manufacturer: Panasonic; Power_W: 100mW; TempCo: 100 ppm/C; Value_Code: 10k0; U/M: EA; Value: 10.0k; EIA_Code: E96; Res_ohm: 10k; SizeX_mm: 1.6; SizeY_mm: 0.8; SizeZ_mm: 1; Value2: 0.1W; SizeArea_mm2: 1.28; VDC_V: 75V; AEC Category: Q200
SR1-SR8 = CMP-0087973-1: MOSFET N-CH TO220-3; Manufacturer: Infineon Technologies; SizeZ_mm: 4.4mm; Symbol Name: SYM-IPP120N08S403AKSA1_hr; QgTyp_nC: 128nC @ 10V; IdsMax_A: 120A; Rdson45_ohm: 2.4m; ChMode: False; VdsMax_V: 80V; AEC Qualified: Yes; Vgs_V: 20V
T1 T8 = CMP-0085494-1: Current Sense Transformer, 8.5 mH, 254 Vµs, 40 A, AEC-Q200 Grade 1, SMT; Manufacturer: Coilcraft; SizeArea_mm2: 289.6905; Lp: 8500; SizeX_mm: 19.91; Ns1toNp: 100; SizeY_mm: 14.55; SizeAreaWB_mm2: 362.6105; AEC Grade: 1; Value: 8.5mH; Rsec1_ohm: 1.45; SizeZ_mm: 10.5; DCR_ohm: 360µ; AEC Category: Q200; AEC Qualified: Y
T2-T5 T7 T9 = CMP-0077156-1: Terminal 125A Lug; Manufacturer: Panduit; Voltage_V: 600V; ContactFinish: Copper; Cert_CULUS: Y; CT: False; CompType: Screw Terminal
T6 = 7G08B-100M-R: Coupled inductor, 10 µH, 4.3 A, 0.04 ohm, SMD; Manufacturer: Sagami Elec Co Ltd; SymbolCreator: a0412235; Value: 10uH; Ind_H: 10.0E-6; DCR_ohm: 0.04; AEC Category: Q200; ValueDisplayed: 10µH
TP1 TP4 = CMP-0055142-1: Test Point, Compact, Red, TH; Manufacturer: Keystone; CNHeader: FALSE; Green_Lifecycle: Active; Green_REACh: Passed; ContactFinish: Silver; CT: TRUE
U9 = CMP-0075735-1: High/Low Side, Bi-Directional Zero-Drift Current Sense Amp w/ Enhanced PWM Rejection, PW0008A (TSSOP-8); Alternate Manufacturer: Texas Instruments; SizeX_mm: 6.4; CompType: IC; SizeAreaWB_mm2: 42.0; SizeZ_mm: 1.2; SizeY_mm: 3.0; U/M: EA; SizeArea_mm2: 19.2
U10 = CMP-0860809-1: Automotive, 110-V Common-Mode, High-Voltage, High-Bandwidth, Zero-Drift, Unidirectional, Current-Sense Amplifier, DBV0005A (SOT-23-5); Alternate Manufacturer: Texas Instruments; SizeZ_mm: 1.45; CompType: IC; AEC Category: Q200; SizeArea_mm2: 8.12; SizeY_mm: 2.9; SizeAreaWB_mm2: 14.82; SizeX_mm: 2.8

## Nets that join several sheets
5Vs: TIDM-02009_DCDC_C2000 (6 pins), TIDM-02009_DCDC_Control (8 pins)
+3V3: TIDM-02009_DCDC_C2000 (R16.1 R19.2 R39.1 R95.2), TIDM-02009_DCDC_Control (12 pins), TIDM-02009_DCDC_Power Stage (7 pins)
AGND: TIDM-02009_DCDC_C2000 (25 pins), TIDM-02009_DCDC_Control (77 pins), TIDM-02009_DCDC_Power Stage (17 pins)
isoGND: TIDM-02009_DCDC_Control (11 pins), TIDM-02009_DCDC_Power Stage (11 pins)
CS3: TIDM-02009_DCDC_C2000 (J3.14), TIDM-02009_DCDC_Power Stage (D14.1 D16.1 R60.1 R61.1)
CT1: TIDM-02009_DCDC_Control (D2.2), TIDM-02009_DCDC_Power Stage (R14.1 T1.2)
CT2: TIDM-02009_DCDC_Control (R56.1 R62.2 R68.1), TIDM-02009_DCDC_Power Stage (R14.2 T1.4)
Dbus+: TIDM-02009_DCDC_Control (R76.1), TIDM-02009_DCDC_Power Stage (9 pins)
EN_1: TIDM-02009_DCDC_C2000 (J3.60), TIDM-02009_DCDC_Control (J16.15 J20.6 J21.6)
Io_+: TIDM-02009_DCDC_Control (R40.2 R42.2 TP2.1), TIDM-02009_DCDC_Power Stage (42 pins)
Ipri: TIDM-02009_DCDC_C2000 (J3.25), TIDM-02009_DCDC_Control (C41.1 R58.2 R59.1)
PWMA: TIDM-02009_DCDC_C2000 (J3.57), TIDM-02009_DCDC_Control (J16.20 J21.5)
PWMB: TIDM-02009_DCDC_C2000 (J3.59), TIDM-02009_DCDC_Control (J16.22 J21.3)
PWMC: TIDM-02009_DCDC_C2000 (J3.54), TIDM-02009_DCDC_Control (J16.16 J20.5)
PWMD: TIDM-02009_DCDC_C2000 (J3.56), TIDM-02009_DCDC_Control (J16.18 J20.3)
PWME: TIDM-02009_DCDC_C2000 (J3.61), TIDM-02009_DCDC_Control (5 pins)
PWMF: TIDM-02009_DCDC_C2000 (R12.2 R87.1), TIDM-02009_DCDC_Control (5 pins)
SR1_1: TIDM-02009_DCDC_Control (R152.2 R158.2), TIDM-02009_DCDC_Power Stage (SR5.1)
SR1_2: TIDM-02009_DCDC_Control (R155.2 R157.2), TIDM-02009_DCDC_Power Stage (SR6.1)
SR1_3: TIDM-02009_DCDC_Control (R168.2 R173.2), TIDM-02009_DCDC_Power Stage (SR7.1)
SR1_4: TIDM-02009_DCDC_Control (R170.2 R172.2), TIDM-02009_DCDC_Power Stage (SR8.1)
SR2_1: TIDM-02009_DCDC_Control (R153.2 R160.2), TIDM-02009_DCDC_Power Stage (SR1.1)
SR2_2: TIDM-02009_DCDC_Control (R156.2 R159.2), TIDM-02009_DCDC_Power Stage (SR2.1)
SR2_3: TIDM-02009_DCDC_Control (R169.2 R175.2), TIDM-02009_DCDC_Power Stage (SR3.1)
SR2_4: TIDM-02009_DCDC_Control (R171.2 R174.2), TIDM-02009_DCDC_Power Stage (SR4.1)
Temp1: TIDM-02009_DCDC_C2000 (J3.26), TIDM-02009_DCDC_Control (C58.1 J16.3 U7.3)
Temp2: TIDM-02009_DCDC_C2000 (J3.23), TIDM-02009_DCDC_Control (C59.1 J16.4 U8.3)
Vfb_Io: TIDM-02009_DCDC_C2000 (J3.20 R91.2), TIDM-02009_DCDC_Control (J16.12), TIDM-02009_DCDC_Power Stage (J18.5 U9.8)
Vfb_Io2: TIDM-02009_DCDC_C2000 (R92.2), TIDM-02009_DCDC_Control (J16.14), TIDM-02009_DCDC_Power Stage (U10.1)
Vfb_Vo: TIDM-02009_DCDC_C2000 (J3.34), TIDM-02009_DCDC_Control (C39.1 J16.8 R57.1 R63.2)
Vfb_Vo2: TIDM-02009_DCDC_C2000 (J3.12), TIDM-02009_DCDC_Control (C40.1 J16.10 R42.1 R86.2)
Vpri: TIDM-02009_DCDC_C2000 (J3.30), TIDM-02009_DCDC_Control (C54.1 R83.2)

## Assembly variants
001: not fitted C44 C71 C72 J18 R11 R92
